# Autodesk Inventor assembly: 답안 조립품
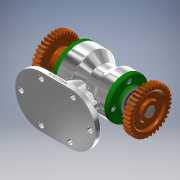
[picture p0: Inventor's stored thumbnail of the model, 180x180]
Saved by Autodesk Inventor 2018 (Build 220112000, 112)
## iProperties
Created: 2020-01
Part Number: 답안 조립품
Document SubType Name: Assembly
Designer: Administrator
Author: Administrator
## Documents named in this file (13)
- C:\Users\Administrator\Desktop\700104v1043\답안 조립품.iam
- C:\Users\Administrator\Desktop\700104v1043\본체.ipt
- C:\Users\Administrator\Desktop\700104v1043\축.ipt
- C:\Users\Administrator\Desktop\700104v1043\키 5 x 5 x 18.ipt
- C:\Users\Administrator\Desktop\700104v1043\베어링 6203.ipt
- C:\Users\Administrator\Desktop\700104v1043\앞커버.ipt
- C:\Users\Administrator\Desktop\700104v1043\뒤커버.ipt
- C:\Users\Administrator\Desktop\700104v1043\오일 실 25 38 8.ipt
- C:\Users\Administrator\Desktop\700104v1043\오일 실 17 30 8.ipt
- C:\Users\Administrator\Desktop\700104v1043\볼트 M4.ipt
- C:\Users\Administrator\Desktop\700104v1043\스퍼기어.ipt
- C:\Users\Administrator\Desktop\700104v1043\멈춤나사 M3.ipt
- C:\Users\Administrator\Desktop\700104v1043\베어링 6205.ipt
